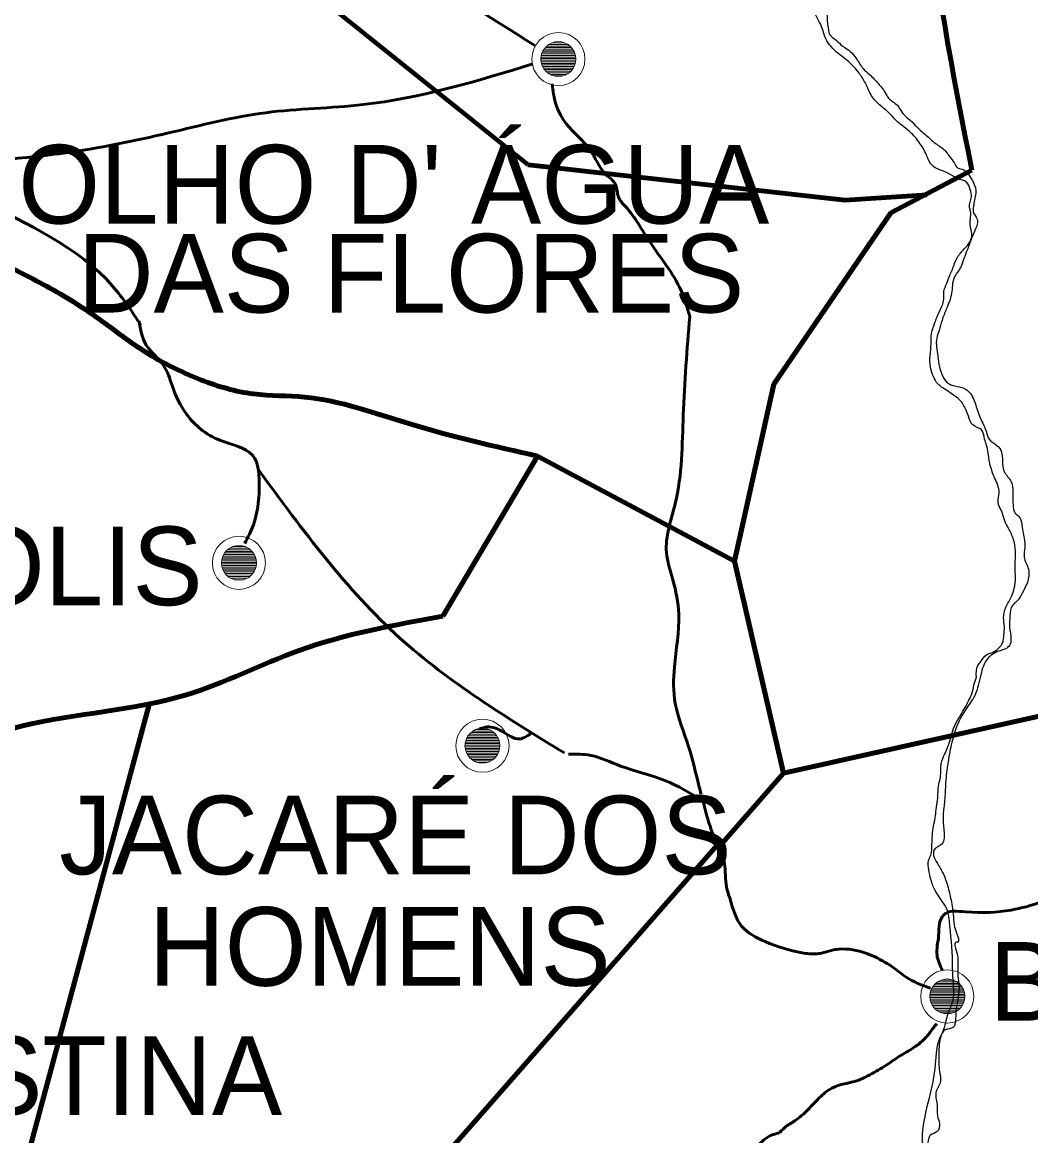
# Model space of a CAD drawing. Extents: x 512883 to 1063249, y 8784064 to 9081064.
# Drawn here: x 688095 to 707317, y 8927073 to 8948300 of the extents above; entities that cross this region are included whole.
import ezdxf

# ---------------------------------------------------------------- set-up
doc = ezdxf.new("R2010")
doc.units = 0
doc.header["$LTSCALE"] = 600
for name, color, linetype, lineweight in [('10', 7, 'Continuous', 53), ('13', 7, 'Continuous', 90), ('20', 7, 'Continuous', 53), ('4', 7, 'Continuous', 13), ('5', 7, 'Continuous', 13)]:
    doc.layers.add(name, color=color, linetype=linetype, lineweight=lineweight)

msp = doc.modelspace()

# ---------------------------------------------------------------- linework, layer by layer
at = {"layer": '10'}
for points in [[(700816.6, 8942693.1), (700652.2, 8943185.8), (700061.2, 8944106.2), (699587.3, 8944793.9), (699459.9, 8944964.6), (699403.8, 8945202.5), (699220.4, 8945399), (698914.7, 8945869.5), (698471.3, 8946355.6), (698267.5, 8946738.3), (698194, 8947123.6)], [(690354.9, 8942526.3), (689817.4, 8943269.9), (687295.1, 8944922.2), (686757.6, 8945211.3), (686340.8, 8945414.9), (685973.5, 8945577)], [(700816.6, 8942693.1), (700693, 8940812.2), (700540.1, 8939121.3), (700372, 8938190.5), (700494.3, 8937678.6), (700606.4, 8937016.7), (700524.8, 8936008.3), (700540.1, 8935315.4), (700794.9, 8934493.2), (700993.6, 8933743.4), (701036.1, 8933582.5)], [(690322.3, 8942610.4), (690456.1, 8942146.4), (690787.3, 8941758.6), (690950.3, 8941375.9), (691225.5, 8940827.8), (691862.4, 8940331.3), (692484.1, 8940046.9), (692611.5, 8939416.1), (692499.4, 8938718), (692336.3, 8938366.3)], [(692609, 8939750.7), (695293, 8936561.1), (698430.6, 8934369.6)], [(697805.9, 8934752.1), (697574.5, 8934638), (697233.1, 8934788), (696958, 8934865.6), (696810.2, 8934829.4)], [(701069.7, 8933455.2), (700341.4, 8933846.9), (699500.6, 8934120.9), (698929.9, 8934322.6), (698507.1, 8934350)], [(705631.1, 8930230.6), (705530.4, 8930515.7), (705560.6, 8930887.2), (705580.7, 8931126.5), (705651.2, 8931279.2), (706079.1, 8931340.2), (706945, 8931375.9), (707518.9, 8931533.7), (708027.3, 8931813.6), (708611.3, 8932246.3), (709220.4, 8932622.9), (710076.2, 8933014.9), (710730.7, 8933233.8), (711173.7, 8933376.3), (711531.1, 8933529), (711651.9, 8933641), (711767.7, 8933839.5)], [(701072.5, 8933444.7), (701126.1, 8933241.8), (701304.5, 8932709.2), (701477.7, 8932264.5), (701518.5, 8931814.6), (701589.8, 8931581.9)], [(701589.8, 8931581.9), (701805.1, 8931070.5), (702253.2, 8930775.2), (702957.9, 8930561.5), (703239.8, 8930541.1), (703602.3, 8930622.6), (704115.8, 8930571.7), (704543.7, 8930378.2), (704805.5, 8930200.1), (704941.4, 8930098.3), (705407, 8929884.1)], [(702542.1, 8927145.8), (702650.8, 8927247.8), (702847.2, 8927375.1), (703033.4, 8927532.9), (703285.2, 8927792.5), (703526.8, 8927980.8), (704020.1, 8928128.4), (704251.7, 8928235.3), (704563.8, 8928418.6), (704805.5, 8928581.4), (705042.1, 8928724), (705248.5, 8928876.7), (705394.5, 8929039.6), (705485.1, 8929161.7), (705525.3, 8929207.5)], [(699180.2, 8922335.2), (699279.3, 8922437.7), (700515.1, 8923808), (701074.5, 8924523), (701338.9, 8925044.3), (701496.6, 8925640.1), (701700, 8926116.7), (701878, 8926494), (702091.5, 8926841.5), (702406.8, 8927094.8), (702534, 8927139.4), (702559.4, 8927159.3)]]:
    msp.add_spline(points, degree=3, dxfattribs=at)
at = {"layer": '13'}
for p, q in [((687755.8, 8953591.1), (697735.1, 8945585.3)), ((696113.8, 8936977.5), (697917.7, 8940030.2)), ((702603.1, 8933984.9), (712216.4, 8936132.7)), ((690521.2, 8935319.2), (687473.3, 8923993.3)), ((693793.1, 8924010.3), (701341.8, 8932609.5))]:
    msp.add_line(p, q, dxfattribs=at)
for points in [[(705341.3, 8945013.4), (703779.5, 8944911.3), (697735.1, 8945585.3)], [(701670.1, 8938028.7), (702420.6, 8941398.5), (704651.7, 8944666.2), (706193.2, 8945483.1)], [(701360.5, 8932563.1), (702603.1, 8933984.9), (701670.1, 8938028.7), (697917.7, 8940030.2)]]:
    msp.add_lwpolyline(points, dxfattribs=at)
for points in [[(706193.2, 8945483.1), (705605, 8948689.6), (704935.7, 8952345.3), (703718.7, 8955735.6), (702857.6, 8958494.4)], [(697917.7, 8940030.2), (695483.7, 8940642.8), (693475.6, 8941153.4), (692502.1, 8941214.7), (691508.2, 8941480.2), (690352, 8942072.5), (689439.3, 8942726), (688425.1, 8943338.7), (687411, 8943890.1), (686640.2, 8944421.1), (686133.1, 8944850), (685950.6, 8945197.2), (685281.2, 8945626.1), (684530.7, 8946136.7), (683760, 8946504.3), (683151.5, 8946892.3), (682482.1, 8947362.1), (681691.1, 8947913.5), (680940.6, 8948117.7), (679804.7, 8948342.4), (678932.6, 8948669.2), (678381, 8948825.9)], [(680828.7, 8933919), (683954.5, 8933899.9), (685486.5, 8934104.2), (688100.7, 8934885), (691225.8, 8935479.3), (693370.2, 8936322.6), (696113.8, 8936977.5)]]:
    msp.add_spline(points, degree=3, dxfattribs=at)
at = {"layer": '20'}
for points in [[(689387.2, 8953163.3), (691341.7, 8951522.8), (693270.8, 8950625.6), (695174.5, 8949549.1), (697867.2, 8947854.1)], [(687492.6, 8945658.8), (688879.6, 8945806.7), (690884.8, 8946191.2), (692737.8, 8946575.7), (694590.7, 8946729.4), (697823.6, 8947505.2)]]:
    msp.add_spline(points, degree=3, dxfattribs=at)
at = {"layer": '4', "lineweight": 25}
for points in [[(706280.5, 8935814.4), (706310.7, 8936038.4), (706366.1, 8936114.7), (706471.8, 8936242), (706622.8, 8936303.1), (706713.4, 8936379.4), (706778.9, 8936465.9), (706804, 8936618.6), (706814.1, 8936781.5), (706799, 8936944.4), (706844.3, 8937148), (706950, 8937351.6), (706995.3, 8937478.9), (707020.5, 8937616.3), (707020.5, 8937931.9), (707025.5, 8938216.9), (706990.3, 8938435.8), (706894.6, 8938649.6), (706814.1, 8938817.5), (706763.8, 8938970.2), (706693.3, 8939153.5), (706713.4, 8939331.6), (706627.8, 8939616.7), (706517.1, 8939993.3), (706476.8, 8940232.6), (706436.5, 8940354.7), (706381.2, 8940527.8), (706210, 8940624.5), (706129.5, 8940792.5), (706079.1, 8940919.7), (705968.4, 8941097.9), (705812.3, 8941215), (705686.4, 8941301.5), (705595.8, 8941362.6), (705540.5, 8941413.5), (705480, 8941505.1), (705419.6, 8941668), (705394.5, 8941897), (705414.6, 8942110.8), (705424.7, 8942365.3), (705485.1, 8942558.7), (705575.7, 8942787.8), (705661.3, 8943016.8), (705661.3, 8943164.4), (705716.7, 8943327.3), (705767, 8943459.7), (705812.3, 8943561.5), (705902.9, 8943785.4), (706028.8, 8943958.5), (706109.3, 8944045), (706159.7, 8944121.4), (706189.9, 8944187.6), (706164.7, 8944431.9), (706169.7, 8944589.7), (706169.7, 8944691.5), (706149.6, 8944767.8), (706184.8, 8944971.4), (706164.7, 8945108.8), (706094.2, 8945251.4), (705923.1, 8945317.5), (705751.9, 8945419.3), (705525.3, 8945511), (705419.6, 8945592.4), (705374.3, 8945663.7), (705334.1, 8945760.4), (705263.6, 8945897.8), (705087.4, 8946137), (704906.2, 8946299.9), (704740, 8946437.3), (704619.2, 8946569.7), (704458.1, 8946707.1), (704281.9, 8946900.6), (704171.2, 8947129.6), (704050.3, 8947323), (703949.7, 8947445.2), (703793.6, 8947592.8), (703642.6, 8947709.9), (703511.7, 8947837.1), (703411, 8947984.7), (703325.4, 8948229.1), (703189.5, 8948539.6), (703194.5, 8948651.5), (703184.5, 8948855.1), (703154.3, 8948977.3), (703070.3, 8949270.7)], [(703346.2, 8949332.2), (703306.6, 8949057.1), (703254.9, 8948814.4), (703275.1, 8948748.2), (703283.7, 8948698.3), (703421.1, 8948498.8), (703436.2, 8948320.7), (703456.3, 8948193.4), (703476.5, 8948081.4), (703612.4, 8947954.2), (703728.2, 8947847.3), (703783.5, 8947811.7), (703904.3, 8947715), (704005, 8947592.8), (704120.8, 8947419.7), (704246.7, 8947302.7), (704412.8, 8947129.6), (704538.7, 8946966.7), (704609.1, 8946849.7), (704775.3, 8946717.3), (704881, 8946559.5), (705027, 8946427.2), (705137.7, 8946310.1), (705344.1, 8946126.9), (705525.3, 8945974.2), (705701.6, 8945836.7), (705767, 8945740), (705862.6, 8945612.8), (705918, 8945526.2), (706008.6, 8945500.8), (706129.5, 8945399), (706205, 8945281.9), (706270.4, 8945093.6), (706270.4, 8945042.7), (706245.2, 8944910.3), (706225.1, 8944788.2), (706220.1, 8944691.5), (706295.6, 8944543.8), (706295.6, 8944452.2), (706260.3, 8944350.4), (706189.9, 8944182.5), (706104.3, 8943953.4), (706043.9, 8943795.6), (705988.5, 8943642.9), (705857.6, 8943434.2), (705807.3, 8943128.8), (705706.6, 8942833.6), (705626, 8942614.7), (705570.7, 8942426.4), (705525.3, 8942278.8), (705545.5, 8941937.7), (705575.7, 8941734.1), (705621, 8941591.6), (705726.7, 8941428.7), (705872.7, 8941367.7), (706074.1, 8941306.6), (706184.8, 8941194.6), (706290.5, 8940935), (706401.3, 8940655.1), (706471.8, 8940492.2), (706522.1, 8940349.7), (706673.1, 8940232.6), (706758.7, 8940105.3), (706778.9, 8939937.3), (706819.1, 8939718.5), (706945, 8939540.3), (706975.2, 8939336.7), (706980.2, 8939092.4), (707015.5, 8938949.9), (707111.1, 8938853.2), (707151.4, 8938680.1), (707191.7, 8938466.3), (707201.7, 8938288.2), (707191.7, 8938099.8), (707272.2, 8937875.9), (707252.1, 8937621.4), (707196.7, 8937499.2), (707111.1, 8937336.3), (707040.6, 8937249.8), (706970.2, 8937183.6), (706919.8, 8936985.1), (706914.8, 8936771.3), (706940, 8936537.2), (706914.8, 8936420.1), (706703.3, 8936308.1), (706491.9, 8936165.6), (706366.1, 8935860.2), (706250.3, 8935468.3), (706074.1, 8935193.4), (705862.6, 8934755.7), (705772, 8934389.2)], [(703249.9, 8922005.1), (703315.3, 8922091.6), (703365.7, 8922234.1), (703406, 8922351.2), (703446.2, 8922493.7), (703491.6, 8922631.2), (703541.9, 8922763.5), (703602.3, 8922839.9), (703657.7, 8922946.8), (703708, 8923007.8), (703843.9, 8923079.1), (703964.8, 8923140.2), (704025.2, 8923206.3), (704060.4, 8923247.1), (704176.2, 8923328.5), (704231.6, 8923399.8), (704332.2, 8923486.3), (704473.2, 8923588.1), (704659.5, 8923761.2), (704795.4, 8923908.8), (704931.3, 8924071.7), (705027, 8924239.6), (705087.4, 8924422.9), (705137.7, 8924677.4), (705157.9, 8924886.1), (705137.7, 8924998), (705087.4, 8925150.7), (705082.3, 8925272.9), (705072.3, 8925481.6), (705147.8, 8925756.5), (705213.2, 8925990.6), (705213.2, 8926250.2), (705218.3, 8926458.9), (705253.5, 8926759.2), (705253.5, 8927013.7), (705495.2, 8928357.5), (705575.7, 8928912.3), (705666.3, 8929121), (705741.8, 8929400.9), (705827.4, 8929619.8), (705847.5, 8929899.8), (705837.5, 8930062.7), (705827.4, 8930251), (705827.4, 8930383.3), (705767, 8931167.2), (705741.8, 8931330.1), (705651.2, 8931508.2), (705495.2, 8931747.4), (705414.6, 8931956.2), (705374.3, 8932144.5), (705369.3, 8932317.5), (705409.6, 8932419.3), (705434.7, 8932633.1), (705464.9, 8932974.2), (705495.2, 8933131.9), (705515.3, 8933294.8), (705540.5, 8933473), (705565.6, 8933773.3), (705595.8, 8933910.7), (705600.9, 8934053.2), (705641.1, 8934267), (705706.6, 8934409.6), (705777.1, 8934603), (705817.3, 8934750.6), (705882.8, 8934923.7), (705983.5, 8935096.7), (706064, 8935234.1), (706139.5, 8935376.7), (706194.9, 8935498.8), (706235.2, 8935666.8), (706280.5, 8935814.4)], [(705772, 8934389.2), (705731.8, 8934134.7), (705691.5, 8933752.9), (705671.3, 8933427.2), (705646.2, 8933157.4), (705661.3, 8932892.7), (705621, 8932633.1), (705475, 8932521.1), (705475, 8932378.6), (705560.6, 8932225.9), (705676.4, 8932002), (705756.9, 8931742.4), (705817.3, 8931452.2), (705842.5, 8931243.5), (705887.8, 8930978.9), (705908, 8930760), (705902.9, 8930760), (705902.9, 8930581.8), (705928.1, 8930327.3), (705928.1, 8930113.6), (705948.2, 8929930.3), (705913, 8929584.2), (705887.8, 8929406), (705872.7, 8929202.4), (705842.5, 8929141.3), (705686.4, 8929090.4), (705595.8, 8928942.8), (705565.6, 8928591.6), (705565.6, 8928418.6), (705585.8, 8928260.8), (705590.8, 8928072.4), (705515.3, 8927924.8), (705530.4, 8927665.2), (705540.5, 8927451.4), (705575.7, 8927303.8), (705535.4, 8927151.1), (705404.5, 8927085), (705359.2, 8926973), (705329, 8926774.5), (705329, 8926479.2), (705354.2, 8926280.7), (705329, 8926072), (705298.8, 8925904.1), (705313.9, 8925736.1), (705313.9, 8925466.3), (705303.8, 8925267.8), (705268.6, 8925099.8), (705213.2, 8924926.8), (705203.2, 8924718.1), (705198.1, 8924422.9), (705188.1, 8924260), (705072.3, 8924030.9), (704966.6, 8923817.2), (704790.4, 8923664.4), (704493.3, 8923389.6), (704333.1, 8923283.1)]]:
    msp.add_spline(points, degree=3, dxfattribs=at)
at = {"layer": '5'}
for p, q in [((698021.2, 8947757), (698605.9, 8947757)), ((698039.5, 8947787), (698587.6, 8947787)), ((698063.5, 8947817), (698563.9, 8947817)), ((698092.6, 8947847), (698534.2, 8947847)), ((698132.2, 8947877), (698494.6, 8947877)), ((698189.5, 8947907), (698437.3, 8947907)), ((697981, 8947607), (698645.8, 8947607)), ((697981.6, 8947577), (698645.5, 8947577)), ((697983.1, 8947637), (698643.7, 8947637)), ((697984.6, 8947547), (698642.2, 8947547)), ((697987.9, 8947667), (698638.9, 8947667)), ((697996, 8947697), (698630.8, 8947697)), ((698006.8, 8947727), (698620, 8947727.3)), ((697990.6, 8947517), (698636.2, 8947517)), ((697999.6, 8947487), (698627.2, 8947487)), ((698012.2, 8947457), (698614.9, 8947457.3)), ((698028.1, 8947427), (698598.7, 8947427)), ((698048.8, 8947397), (698578.3, 8947397.3)), ((698074, 8947366.7), (698553.1, 8947367)), ((698107.3, 8947337), (698519.5, 8947337)), ((698152.3, 8947307), (698474.5, 8947307)), ((698226.1, 8947277), (698400.4, 8947277)), ((691950.3, 8938183), (692498.4, 8938183)), ((691974.3, 8938213), (692474.7, 8938213)), ((692003.4, 8938243), (692445, 8938243)), ((692043, 8938273), (692405.4, 8938273)), ((692100.3, 8938303), (692348.1, 8938303)), ((691891.8, 8938003), (692556.6, 8938003)), ((691892.4, 8937973), (692556.3, 8937973)), ((691893.9, 8938033), (692554.5, 8938033)), ((691898.7, 8938063), (692549.7, 8938063)), ((691906.8, 8938093), (692541.6, 8938093)), ((691917.6, 8938123), (692530.8, 8938123.3)), ((691932, 8938153), (692516.7, 8938153)), ((691895.4, 8937943), (692553, 8937943)), ((691901.4, 8937913), (692547, 8937913)), ((691910.4, 8937883), (692538, 8937883)), ((691923, 8937853), (692525.7, 8937853.3)), ((691938.9, 8937823), (692509.5, 8937823)), ((691959.6, 8937793), (692489.1, 8937793.3)), ((691984.8, 8937762.7), (692463.9, 8937763)), ((692018.1, 8937733), (692430.3, 8937733)), ((692063.1, 8937703), (692385.3, 8937703)), ((692136.9, 8937673), (692311.2, 8937673)), ((696685, 8934787.8), (697047.4, 8934787.8)), ((696742.3, 8934817.8), (696990.1, 8934817.8)), ((696540.7, 8934577.8), (697191.7, 8934577.8)), ((696548.8, 8934607.8), (697183.6, 8934607.8)), ((696559.6, 8934637.8), (697172.8, 8934638.1)), ((696574, 8934667.8), (697158.7, 8934667.8)), ((696592.3, 8934697.8), (697140.4, 8934697.8)), ((696616.3, 8934727.8), (697116.7, 8934727.8)), ((696645.4, 8934757.8), (697087, 8934757.8)), ((696533.8, 8934517.8), (697198.6, 8934517.8)), ((696534.4, 8934487.8), (697198.3, 8934487.8)), ((696535.9, 8934547.8), (697196.5, 8934547.8)), ((696537.4, 8934457.8), (697195, 8934457.8)), ((696543.4, 8934427.8), (697189, 8934427.8)), ((696552.4, 8934397.8), (697180, 8934397.8)), ((696565, 8934367.8), (697167.7, 8934368.1)), ((696580.9, 8934337.8), (697151.5, 8934337.8)), ((696601.6, 8934307.8), (697131.1, 8934308.1)), ((696626.8, 8934277.4), (697105.9, 8934277.8)), ((696660.1, 8934247.8), (697072.3, 8934247.8)), ((696705.1, 8934217.8), (697027.3, 8934217.8)), ((696778.9, 8934187.8), (696953.2, 8934187.8)), ((705452.8, 8929916.9), (706000.9, 8929916.9)), ((705476.8, 8929946.9), (705977.2, 8929946.9)), ((705505.9, 8929976.9), (705947.5, 8929976.9)), ((705545.5, 8930006.9), (705907.9, 8930006.9)), ((705602.8, 8930036.9), (705850.6, 8930036.9)), ((705394.3, 8929736.9), (706059.1, 8929736.9)), ((705394.9, 8929706.9), (706058.8, 8929706.9)), ((705396.4, 8929766.9), (706057, 8929766.9)), ((705401.2, 8929796.9), (706052.2, 8929796.9)), ((705409.3, 8929826.9), (706044.1, 8929826.9)), ((705420.1, 8929856.9), (706033.3, 8929857.2)), ((705434.5, 8929886.9), (706019.2, 8929886.9)), ((705397.9, 8929676.9), (706055.5, 8929676.9)), ((705403.9, 8929646.9), (706049.5, 8929646.9)), ((705412.9, 8929616.9), (706040.5, 8929616.9)), ((705425.5, 8929586.9), (706028.2, 8929587.2)), ((705441.4, 8929556.9), (706012, 8929556.9)), ((705462.1, 8929526.9), (705991.6, 8929527.2)), ((705487.3, 8929496.6), (705966.4, 8929496.9)), ((705520.6, 8929466.9), (705932.8, 8929466.9)), ((705565.6, 8929436.9), (705887.8, 8929436.9)), ((705639.4, 8929406.9), (705813.7, 8929406.9))]:
    msp.add_line(p, q, dxfattribs=at)
for centre, radius in [((698313.5, 8947598), 506.1), ((698313.5, 8947598), 332.9), ((692224.3, 8937994), 506.1), ((692224.3, 8937994), 332.9), ((696866.3, 8934508.7), 506.1), ((696866.3, 8934508.7), 332.9), ((705726.8, 8929727.9), 506.1), ((705726.8, 8929727.9), 332.9)]:
    msp.add_circle(centre, radius, dxfattribs=at)

# ---------------------------------------------------------------- texts
for s, p in [("OLHO D' ÁGUA", (688018.3, 8944462.4)), ('DAS FLORES', (689149.5, 8942766.6)), ('MONTEIRÓPOLIS', (674815.8, 8937186.6)), ('JACARÉ DOS ', (688798.7, 8932056.1)), ('HOMENS', (690506.1, 8929931.8)), ('BATALHA', (706526.6, 8929265.9)), ('PALESTINA', (682012.2, 8927470.7))]:
    msp.add_text(s, height=1500, dxfattribs=at).set_placement(p)

doc.saveas('drawing.dxf')
